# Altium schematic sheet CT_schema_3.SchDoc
size 276 x 169 mm
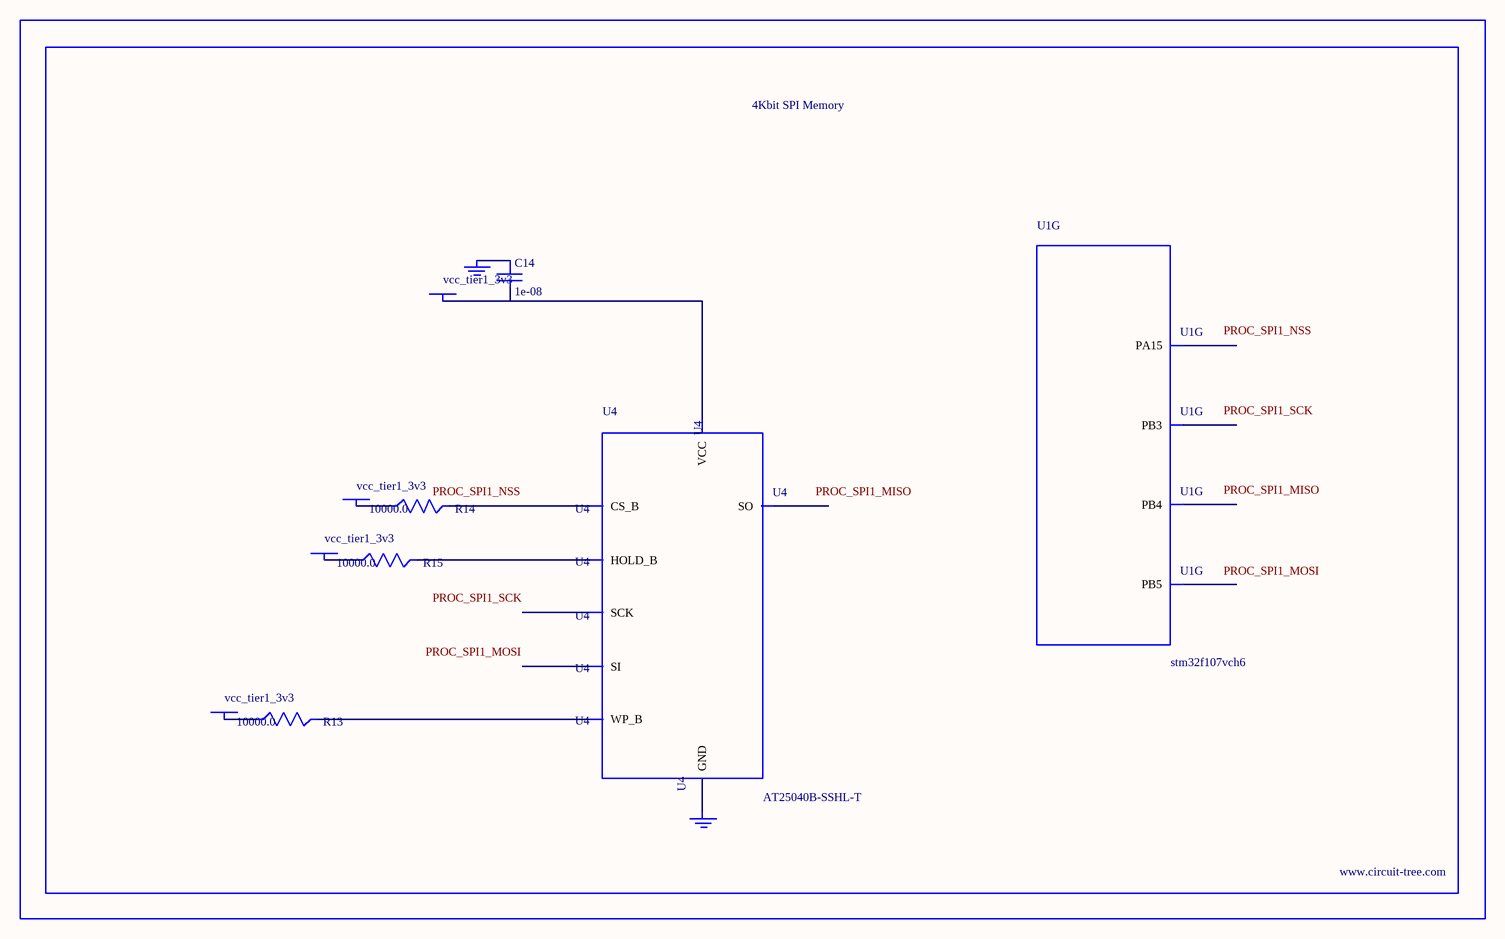
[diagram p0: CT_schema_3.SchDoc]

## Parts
BORDER2  (no value)
C14  1e-08  [C0402]
GND_INSTANCE_2_0  (no value)
GND_INSTANCE_2_1  (no value)
POWER_INSTANCE_2_0  vcc_tier1_3v3
POWER_INSTANCE_2_1  vcc_tier1_3v3
POWER_INSTANCE_2_2  vcc_tier1_3v3
POWER_INSTANCE_2_3  vcc_tier1_3v3
R13  10000.0  [R0603]
R14  10000.0  [R0603]
R15  10000.0  [R0603]
U1  stm32f107vch6  [LFBGA100]  (part G of 9)
U4  AT25040B-SSHL-T  [SOIC-8]

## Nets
NetC14_1: C14.1 GND_INSTANCE_2_0.0(GND)
NetC14_2: C14.2 POWER_INSTANCE_2_3.0(PWR) U4.8(VCC)
NetGND_INSTANCE_2_1_0: GND_INSTANCE_2_1.0(GND) U4.4(GND)
NetPOWER_INSTANCE_2_0_0: POWER_INSTANCE_2_0.0(PWR) R14.1
NetPOWER_INSTANCE_2_1_0: POWER_INSTANCE_2_1.0(PWR) R13.1
NetPOWER_INSTANCE_2_2_0: POWER_INSTANCE_2_2.0(PWR) R15.1
NetR13_2: R13.2 U4.3(WP_B)
NetR14_2: R14.2 U4.1(CS_B)
NetR15_2: R15.2 U4.7(HOLD_B)

Not connected (* = marked no-connect by the designer): U1 A6(PB4) A7(PB3) A8(PA15) C5(PB5); U4 2(SO) 5(SI) 6(SCK)

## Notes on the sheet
- Labels drawn without touching a wire or pin: PROC_SPI1_MISO, PROC_SPI1_MOSI, PROC_SPI1_NSS, PROC_SPI1_SCK

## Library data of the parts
BORDER2 = BORDER_PAGE2
C14 = C0402C103K3RAC
GND_INSTANCE_2_0 GND_INSTANCE_2_1 = GND
POWER_INSTANCE_2_0-POWER_INSTANCE_2_3 = PWR
R13-R15 = RC0603JR-0710KL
